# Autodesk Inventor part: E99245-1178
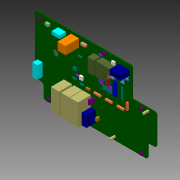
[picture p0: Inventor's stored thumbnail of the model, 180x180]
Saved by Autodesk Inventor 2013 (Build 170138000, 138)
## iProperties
Created: 2004-11
Part Number: E99245-1178
Document SubType Name: Modeling
Designer: Autodesk, Inc.
Manufacturer: Standard
Standards Organization: Custom
Description: CONTROLER CARD, 29 SERIES
Engineer: N. GINEER
Mass: 79.5696 g
Surface Area: 565.686 cm^2
Volume: 79.5696 cm^3
Density: 1 g/cm^3
Material: Allgemein
CAGE: 1LJX3
Dept. ID: Product Design
Description #2: ---
Finish #1: ---
Finish #2: ---
Material ID: ---
Project Number: ---
Author: Autodesk, Inc.
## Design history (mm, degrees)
sketch "Sketch1"
  geometry: L1 (182, 2)-(182, 20); L2 (182, 20)-(185, 23); L3 (185, 23)-(194, 23); L4 (194, 23)-(196, 25); L5 (196, 25)-(196, 70); L6 (196, 70)-(194, 72); L7 (194, 72)-(158.5, 72); L8 (157, 73.5)-(157, 116); L9 (157, 116)-(155, 118); L10 (155, 118)-(2, 118); L11 (2, 118)-(0, 116); L12 (0, 116)-(0, 25); L13 (0, 25)-(2, 23); L14 (2, 23)-(11, 23); L15 (11, 23)-(14, 20); L16 (14, 20)-(14, 2); L17 (14, 2)-(16, 0); L18 (16, 0)-(180, 0); L19 (180, 0)-(182, 2); C1 r 1.753 at (22.987, 3.988); C2 r 1.753 at (172.999, 3.988); C3 r 1.753 at (172.999, 66.98); C4 r 1.753 at (113.005, 113.995); C5 r 1.753 at (8.992, 110.007); C6 r 0.508 at (137.312, 106.68); C7 r 0.508 at (152.248, 106.68); C8 r 0.394 at (103.505, 19.685); C9 r 0.394 at (103.505, 17.145); C10 r 0.508 at (94.615, 25.883); C11 r 0.508 at (94.615, 10.947); C12 r 0.483 at (83.82, 41.275); C13 r 0.483 at (83.82, 12.065); C14 r 0.394 at (95.25, 42.545); C15 r 0.394 at (95.25, 37.465); C16 r 0.483 at (69.85, 41.275); C17 r 0.483 at (69.85, 12.065); C18 r 0.394 at (61.595, 17.145); C19 r 0.394 at (61.595, 12.065); C20 r 0.483 at (53.34, 41.275); C21 r 0.483 at (53.34, 12.065); C22 r 0.635 at (100.33, 109.22); C23 r 0.635 at (100.33, 78.74); C24 r 0.635 at (106.045, 100.965); C25 r 0.635 at (136.525, 100.965); C26 r 0.635 at (113.665, 109.855); C27 r 0.635 at (113.665, 79.375); C28 r 0.432 at (62.23, 107.315); C29 r 0.432 at (67.31, 107.315); C30 r 0.356 at (120.65, 107.95); C31 r 0.356 at (120.65, 97.79); C32 r 0.533 at (73.66, 110.49); C33 r 0.533 at (87.63, 110.49); C34 r 0.508 at (16.51, 109.855); C35 r 0.508 at (27.94, 109.855); C36 r 0.711 at (55.245, 109.855); C37 r 0.711 at (50.165, 109.855); C38 r 0.711 at (37.465, 109.855); C39 r 0.711 at (32.385, 109.855); C40 r 0.432 at (127, 81.28); C41 r 0.432 at (127, 78.74); C42 r 0.432 at (127, 76.2); C43 r 0.432 at (127, 73.66); C44 r 0.432 at (127, 71.12); C45 r 0.432 at (127, 68.58); C46 r 0.432 at (127, 66.04); C47 r 0.432 at (134.62, 66.04); C48 r 0.432 at (134.62, 68.58); C49 r 0.432 at (134.62, 71.12); C50 r 0.432 at (134.62, 73.66); C51 r 0.432 at (134.62, 76.2); C52 r 0.432 at (134.62, 78.74); C53 r 0.432 at (134.62, 81.28); C54 r 0.432 at (115.57, 81.915); C55 r 0.432 at (115.57, 79.375); C56 r 0.432 at (115.57, 76.835); C57 r 0.432 at (115.57, 74.295); C58 r 0.432 at (123.19, 74.295); C59 r 0.432 at (123.19, 76.835); C60 r 0.432 at (123.19, 79.375); C61 r 0.432 at (123.19, 81.915); C62 r 0.47 at (129.413, 5.715); C63 r 0.47 at (183.515, 68.58); C64 r 0.47 at (126.365, 92.71); A1 r 1.5 centre (158.5, 73.5) between (157, 73.5) and (158.5, 72)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
  constraints: 148 centre point, 38 end point, 2 point on circle
extrude "example2.max_Outline" join sketch "Sketch1" distance "d0" = 1.5748; taper "d1" = 0 deg
sketch "3.5MTH, 0_1"
  geometry: L1 (21.082, 2.083)-(21.082, 5.893); L2 (21.082, 5.893)-(24.892, 5.893); L3 (24.892, 5.893)-(24.892, 2.083); L4 (24.892, 2.083)-(21.082, 2.083)
  constraints: 8 end point
extrude "11_2" join sketch "3.5MTH, 0_1" distance "d58" = 2.54; taper "d59" = 0 deg
sketch "3.5MTH, 0_3"
  geometry: L1 (171.094, 2.083)-(171.094, 5.893); L2 (171.094, 5.893)-(174.904, 5.893); L3 (174.904, 5.893)-(174.904, 2.083); L4 (174.904, 2.083)-(171.094, 2.083)
  constraints: 8 end point
extrude "21_4" join sketch "3.5MTH, 0_3" distance "d60" = 2.54; taper "d61" = 0 deg
sketch "3.5MTH, 0_5"
  geometry: L1 (171.094, 65.075)-(171.094, 68.885); L2 (171.094, 68.885)-(174.904, 68.885); L3 (174.904, 68.885)-(174.904, 65.075); L4 (174.904, 65.075)-(171.094, 65.075)
  constraints: 8 end point
extrude "31_6" join sketch "3.5MTH, 0_5" distance "d62" = 2.54; taper "d63" = 0 deg
sketch "3.5MTH, 0_7"
  geometry: L1 (111.1, 112.09)-(111.1, 115.9); L2 (111.1, 115.9)-(114.91, 115.9); L3 (114.91, 115.9)-(114.91, 112.09); L4 (114.91, 112.09)-(111.1, 112.09)
  constraints: 8 end point
extrude "41_8" join sketch "3.5MTH, 0_7" distance "d64" = 2.54; taper "d65" = 0 deg
sketch "3.5MTH, 0_9"
  geometry: L1 (7.087, 108.102)-(7.087, 111.912); L2 (7.087, 111.912)-(10.897, 111.912); L3 (10.897, 111.912)-(10.897, 108.102); L4 (10.897, 108.102)-(7.087, 108.102)
  constraints: 8 end point
extrude "51_10" join sketch "3.5MTH, 0_9" distance "d66" = 2.54; taper "d67" = 0 deg
sketch "RAD_.725X.300_LS.588_.040, 470NF_11"
  geometry: L1 (153.67, 110.49)-(135.89, 110.49); L2 (135.89, 110.49)-(135.89, 102.87); L3 (135.89, 102.87)-(153.67, 102.87); L4 (153.67, 102.87)-(153.67, 110.49)
  constraints: 8 end point
extrude "C1_12" join sketch "RAD_.725X.300_LS.588_.040, 470NF_11" distance "d68" = 15.24; taper "d69" = 0 deg
sketch "SM_C_1206, 10NF_13"
  geometry: L1 (117.602, 62.865)-(119.888, 62.865); L2 (119.888, 62.865)-(119.888, 68.453); L3 (119.888, 68.453)-(117.602, 68.453); L4 (117.602, 68.453)-(117.602, 62.865)
  constraints: 8 end point
extrude "C2_14" join sketch "SM_C_1206, 10NF_13" distance "d70" = 1.27; taper "d71" = 0 deg
sketch "SM_C_1206, 10NF_15"
  geometry: L1 (105.918, 75.565)-(103.632, 75.565); L2 (103.632, 75.565)-(103.632, 69.977); L3 (103.632, 69.977)-(105.918, 69.977); L4 (105.918, 69.977)-(105.918, 75.565)
  constraints: 8 end point
extrude "C3_16" join sketch "SM_C_1206, 10NF_15" distance "d72" = 1.27; taper "d73" = 0 deg
sketch "SM_C_1206, 10NF_17"
  geometry: L1 (112.268, 68.58)-(109.982, 68.58); L2 (109.982, 68.58)-(109.982, 62.992); L3 (109.982, 62.992)-(112.268, 62.992); L4 (112.268, 62.992)-(112.268, 68.58)
  constraints: 8 end point
extrude "C4_18" join sketch "SM_C_1206, 10NF_17" distance "d74" = 1.27; taper "d75" = 0 deg
sketch "SM_C_1206, 10NF_19"
  geometry: L1 (115.062, 62.865)-(117.348, 62.865); L2 (117.348, 62.865)-(117.348, 68.453); L3 (117.348, 68.453)-(115.062, 68.453); L4 (115.062, 68.453)-(115.062, 62.865)
  constraints: 8 end point
extrude "C5_20" join sketch "SM_C_1206, 10NF_19" distance "d76" = 1.27; taper "d77" = 0 deg
sketch "SM_C_1206, 10NF_21"
  geometry: L1 (62.23, 70.993)-(62.23, 68.707); L2 (62.23, 68.707)-(67.818, 68.707); L3 (67.818, 68.707)-(67.818, 70.993); L4 (67.818, 70.993)-(62.23, 70.993)
  constraints: 8 end point
extrude "C6_22" join sketch "SM_C_1206, 10NF_21" distance "d78" = 1.27; taper "d79" = 0 deg
sketch "SM_C_1206, 10NF_23"
  geometry: L1 (62.23, 68.453)-(62.23, 66.167); L2 (62.23, 66.167)-(67.818, 66.167); L3 (67.818, 66.167)-(67.818, 68.453); L4 (67.818, 68.453)-(62.23, 68.453)
  constraints: 8 end point
extrude "C7_24" join sketch "SM_C_1206, 10NF_23" distance "d80" = 1.27; taper "d81" = 0 deg
sketch "SM_C_1206, 10NF_25"
  geometry: L1 (73.66, 53.213)-(73.66, 50.927); L2 (73.66, 50.927)-(79.248, 50.927); L3 (79.248, 50.927)-(79.248, 53.213); L4 (79.248, 53.213)-(73.66, 53.213)
  constraints: 8 end point
extrude "C8_26" join sketch "SM_C_1206, 10NF_25" distance "d82" = 1.27; taper "d83" = 0 deg
sketch "SM_C_1206, 10NF_27"
  geometry: L1 (136.017, 95.885)-(138.303, 95.885); L2 (138.303, 95.885)-(138.303, 101.473); L3 (138.303, 101.473)-(136.017, 101.473); L4 (136.017, 101.473)-(136.017, 95.885)
  constraints: 8 end point
extrude "C9_28" join sketch "SM_C_1206, 10NF_27" distance "d84" = 1.27; taper "d85" = 0 deg
sketch "RAD_.150X.100_LS.100_.031, 1NF_29"
  geometry: L1 (102.133, 20.726)-(102.133, 16.104); L2 (102.133, 16.104)-(104.877, 16.104); L3 (104.877, 16.104)-(104.877, 20.726); L4 (104.877, 20.726)-(102.133, 20.726)
  constraints: 8 end point
extrude "C10_30" join sketch "RAD_.150X.100_LS.100_.031, 1NF_29" distance "d86" = 5.08; taper "d87" = 0 deg
sketch "RAD_.725X.300_LS.588_.040, 470NF_31"
  geometry: L1 (98.425, 9.525)-(98.425, 27.305); L2 (98.425, 27.305)-(90.805, 27.305); L3 (90.805, 27.305)-(90.805, 9.525); L4 (90.805, 9.525)-(98.425, 9.525)
  constraints: 8 end point
extrude "C11_32" join sketch "RAD_.725X.300_LS.588_.040, 470NF_31" distance "d88" = 15.24; taper "d89" = 0 deg
sketch "RAD_1.200X.250_LS1.100_.040, 2.2UF_33"
  geometry: L1 (77.216, 44.069)-(90.424, 44.069); L2 (90.424, 44.069)-(90.424, 9.271); L3 (90.424, 9.271)-(77.216, 9.271); L4 (77.216, 9.271)-(77.216, 44.069)
  constraints: 8 end point
extrude "C12_34" join sketch "RAD_1.200X.250_LS1.100_.040, 2.2UF_33" distance "d90" = 20.828; taper "d91" = 0 deg
sketch "RAD_.300X.100_LS.200_.031, 100PF_35"
  geometry: L1 (93.98, 36.195)-(93.98, 43.815); L2 (93.98, 43.815)-(96.52, 43.815); L3 (96.52, 43.815)-(96.52, 36.195); L4 (96.52, 36.195)-(93.98, 36.195)
  constraints: 8 end point
extrude "C13_36" join sketch "RAD_.300X.100_LS.200_.031, 100PF_35" distance "d92" = 8.255; taper "d93" = 0 deg
sketch "RAD_1.200X.250_LS1.100_.040, 2.2UF_37"
  geometry: L1 (63.246, 44.069)-(76.454, 44.069); L2 (76.454, 44.069)-(76.454, 9.271); L3 (76.454, 9.271)-(63.246, 9.271); L4 (63.246, 9.271)-(63.246, 44.069)
  constraints: 8 end point
extrude "C14_38" join sketch "RAD_1.200X.250_LS1.100_.040, 2.2UF_37" distance "d94" = 20.828; taper "d95" = 0 deg
sketch "RAD_.300X.100_LS.200_.031, 100PF_39"
  geometry: L1 (60.325, 10.795)-(60.325, 18.415); L2 (60.325, 18.415)-(62.865, 18.415); L3 (62.865, 18.415)-(62.865, 10.795); L4 (62.865, 10.795)-(60.325, 10.795)
  constraints: 8 end point
extrude "C15_40" join sketch "RAD_.300X.100_LS.200_.031, 100PF_39" distance "d96" = 8.255; taper "d97" = 0 deg
sketch "RAD_1.200X.250_LS1.100_.040, 2.2UF_41"
  geometry: L1 (46.736, 44.069)-(59.944, 44.069); L2 (59.944, 44.069)-(59.944, 9.271); L3 (59.944, 9.271)-(46.736, 9.271); L4 (46.736, 9.271)-(46.736, 44.069)
  constraints: 8 end point
extrude "C16_42" join sketch "RAD_1.200X.250_LS1.100_.040, 2.2UF_41" distance "d98" = 20.828; taper "d99" = 0 deg
sketch "SM_C_1206, 10NF_43"
  geometry: L1 (120.142, 62.865)-(122.428, 62.865); L2 (122.428, 62.865)-(122.428, 68.453); L3 (122.428, 68.453)-(120.142, 68.453); L4 (120.142, 68.453)-(120.142, 62.865)
  constraints: 8 end point
extrude "C17_44" join sketch "SM_C_1206, 10NF_43" distance "d100" = 1.27; taper "d101" = 0 deg
sketch "SM_C_1206, 10NF_45"
  geometry: L1 (111.252, 75.565)-(113.538, 75.565); L2 (113.538, 75.565)-(113.538, 81.153); L3 (113.538, 81.153)-(111.252, 81.153); L4 (111.252, 81.153)-(111.252, 75.565)
  constraints: 8 end point
extrude "C18_46" join sketch "SM_C_1206, 10NF_45" distance "d102" = 1.27; taper "d103" = 0 deg
sketch "SM_C_1206, 10NF_47"
  geometry: L1 (114.808, 68.58)-(112.522, 68.58); L2 (112.522, 68.58)-(112.522, 62.992); L3 (112.522, 62.992)-(114.808, 62.992); L4 (114.808, 62.992)-(114.808, 68.58)
  constraints: 8 end point
extrude "C19_48" join sketch "SM_C_1206, 10NF_47" distance "d104" = 1.27; taper "d105" = 0 deg
sketch "SM_C_1206, 10NF_49"
  geometry: L1 (142.748, 80.645)-(140.462, 80.645); L2 (140.462, 80.645)-(140.462, 75.057); L3 (140.462, 75.057)-(142.748, 75.057); L4 (142.748, 75.057)-(142.748, 80.645)
  constraints: 8 end point
extrude "C20_50" join sketch "SM_C_1206, 10NF_49" distance "d106" = 1.27; taper "d107" = 0 deg
sketch "SM_C_1206, 10NF_51"
  geometry: L1 (67.31, 53.467)-(67.31, 55.753); L2 (67.31, 55.753)-(61.722, 55.753); L3 (61.722, 55.753)-(61.722, 53.467); L4 (61.722, 53.467)-(67.31, 53.467)
  constraints: 8 end point
extrude "C21_52" join sketch "SM_C_1206, 10NF_51" distance "d108" = 1.27; taper "d109" = 0 deg
sketch "SM_C_1206, 10NF_53"
  geometry: L1 (142.748, 74.93)-(140.462, 74.93); L2 (140.462, 74.93)-(140.462, 69.342); L3 (140.462, 69.342)-(142.748, 69.342); L4 (142.748, 69.342)-(142.748, 74.93)
  constraints: 8 end point
extrude "C22_54" join sketch "SM_C_1206, 10NF_53" distance "d110" = 1.27; taper "d111" = 0 deg
sketch "SM_C_1206, 10NF_55"
  geometry: L1 (142.748, 69.215)-(140.462, 69.215); L2 (140.462, 69.215)-(140.462, 63.627); L3 (140.462, 63.627)-(142.748, 63.627); L4 (142.748, 63.627)-(142.748, 69.215)
  constraints: 8 end point
extrude "C23_56" join sketch "SM_C_1206, 10NF_55" distance "d112" = 1.27; taper "d113" = 0 deg
sketch "SM_C_1206, 10NF_57"
  geometry: L1 (122.682, 62.865)-(124.968, 62.865); L2 (124.968, 62.865)-(124.968, 68.453); L3 (124.968, 68.453)-(122.682, 68.453); L4 (122.682, 68.453)-(122.682, 62.865)
  constraints: 8 end point
extrude "C24_58" join sketch "SM_C_1206, 10NF_57" distance "d114" = 1.27; taper "d115" = 0 deg
sketch "SM_C_1206, 10NF_59"
  geometry: L1 (99.06, 83.312)-(99.06, 85.598); L2 (99.06, 85.598)-(93.472, 85.598); L3 (93.472, 85.598)-(93.472, 83.312); L4 (93.472, 83.312)-(99.06, 83.312)
  constraints: 8 end point
extrude "C25_60" join sketch "SM_C_1206, 10NF_59" distance "d116" = 1.27; taper "d117" = 0 deg
sketch "SM_C_1206, 10NF_61"
  geometry: L1 (76.479, 88.57)-(76.479, 90.856); L2 (76.479, 90.856)-(70.891, 90.856); L3 (70.891, 90.856)-(70.891, 88.57); L4 (70.891, 88.57)-(76.479, 88.57)
  constraints: 8 end point
extrude "C26_62" join sketch "SM_C_1206, 10NF_61" distance "d118" = 1.27; taper "d119" = 0 deg
sketch "AX_1.200X.400_.050, 10UF_63"
  geometry: L1 (95.25, 82.867)-(95.25, 105.092); L2 (95.25, 105.092)-(105.41, 105.093); L3 (105.41, 105.093)-(105.41, 82.868); L4 (105.41, 82.868)-(95.25, 82.867)
  constraints: 8 end point
extrude "C27_64" join sketch "AX_1.200X.400_.050, 10UF_63" distance "d120" = 10.16; taper "d121" = 0 deg
sketch "AX_1.200X.400_.050, 10UF_65"
  geometry: L1 (132.398, 95.885)-(110.173, 95.885); L2 (110.173, 95.885)-(110.173, 106.045); L3 (110.173, 106.045)-(132.398, 106.045); L4 (132.398, 106.045)-(132.398, 95.885)
  constraints: 8 end point
extrude "C28_66" join sketch "AX_1.200X.400_.050, 10UF_65" distance "d122" = 10.16; taper "d123" = 0 deg
sketch "AX_1.200X.400_.050, 10UF_67"
  geometry: L1 (108.585, 83.502)-(108.585, 105.727); L2 (108.585, 105.727)-(118.745, 105.728); L3 (118.745, 105.728)-(118.745, 83.503); L4 (118.745, 83.503)-(108.585, 83.502)
  constraints: 8 end point
extrude "C30_68" join sketch "AX_1.200X.400_.050, 10UF_67" distance "d124" = 10.16; taper "d125" = 0 deg
sketch "CAPTEST, 1MF_69"
  geometry: L1 (58.318, 100.863)-(58.318, 113.767); L2 (58.318, 113.767)-(71.222, 113.767); L3 (71.222, 113.767)-(71.222, 100.863); L4 (71.222, 100.863)-(58.318, 100.863)
  constraints: 8 end point
extrude "C31_70" join sketch "CAPTEST, 1MF_69" distance "d126" = 21.59; taper "d127" = 0 deg
sketch "SM_D_MLL41_12, LL4148_71"
  geometry: L1 (106.68, 83.337)-(106.68, 76.378); L2 (106.68, 76.378)-(108.382, 76.378); L3 (108.382, 76.378)-(108.585, 76.175); L4 (108.585, 76.175)-(108.788, 76.378); L5 (108.788, 76.378)-(110.465, 76.378); L6 (110.465, 76.378)-(110.465, 83.337); L7 (110.465, 83.337)-(106.68, 83.337)
  constraints: 14 end point
extrude "D1_72" join sketch "SM_D_MLL41_12, LL4148_71" distance "d128" = 1.651; taper "d129" = 0 deg
sketch "SM_D_MLL41_12, LL4148_75"
  geometry: L1 (135.255, 97.003)-(135.255, 103.962); L2 (135.255, 103.962)-(133.553, 103.962); L3 (133.553, 103.962)-(133.35, 104.165); L4 (133.35, 104.165)-(133.147, 103.962); L5 (133.147, 103.962)-(131.47, 103.962); L6 (131.47, 103.962)-(131.47, 97.003); L7 (131.47, 97.003)-(135.255, 97.003)
  constraints: 14 end point
extrude "D3_76" join sketch "SM_D_MLL41_12, LL4148_75" distance "d132" = 1.651; taper "d133" = 0 deg
sketch "SM_D_MLL41_12, LL4148_77"
  geometry: L1 (139.065, 101.752)-(139.065, 94.793); L2 (139.065, 94.793)-(140.767, 94.793); L3 (140.767, 94.793)-(140.97, 94.59); L4 (140.97, 94.59)-(141.173, 94.793); L5 (141.173, 94.793)-(142.85, 94.793); L6 (142.85, 94.793)-(142.85, 101.752); L7 (142.85, 101.752)-(139.065, 101.752)
  constraints: 14 end point
extrude "D4_78" join sketch "SM_D_MLL41_12, LL4148_77" distance "d134" = 1.651; taper "d135" = 0 deg
sketch "SM_D_MLL41_12, LL4148_79"
  geometry: L1 (119.863, 86.995)-(126.822, 86.995); L2 (126.822, 86.995)-(126.822, 88.697); L3 (126.822, 88.697)-(127.025, 88.9); L4 (127.025, 88.9)-(126.822, 89.103); L5 (126.822, 89.103)-(126.822, 90.78); L6 (126.822, 90.78)-(119.863, 90.78); L7 (119.863, 90.78)-(119.863, 86.995)
  constraints: 14 end point
extrude "D5_80" join sketch "SM_D_MLL41_12, LL4148_79" distance "d136" = 1.651; taper "d137" = 0 deg
sketch "SM_D_MLL41_12, LL4148_81"
  geometry: L1 (94.463, 90.17)-(101.422, 90.17); L2 (101.422, 90.17)-(101.422, 91.872); L3 (101.422, 91.872)-(101.625, 92.075); L4 (101.625, 92.075)-(101.422, 92.278); L5 (101.422, 92.278)-(101.422, 93.955); L6 (101.422, 93.955)-(94.463, 93.955); L7 (94.463, 93.955)-(94.463, 90.17)
  constraints: 14 end point
extrude "D8_82" join sketch "SM_D_MLL41_12, LL4148_81" distance "d138" = 1.651; taper "d139" = 0 deg
sketch "DAX1_1N_4001-4007, 1N4002_83"
  geometry: L1 (84.455, 108.903)-(84.455, 112.078); L2 (84.455, 112.078)-(76.835, 112.078); L3 (76.835, 112.078)-(76.835, 108.903); L4 (76.835, 108.903)-(84.455, 108.903)
  constraints: 8 end point
extrude "D9_84" join sketch "DAX1_1N_4001-4007, 1N4002_83" distance "d140" = 3.556; taper "d141" = 0 deg
sketch "DAX1_.450X.150_.040, SB130_85"
  geometry: L1 (25.083, 107.95)-(25.083, 111.76); L2 (25.083, 111.76)-(19.367, 111.76); L3 (19.367, 111.76)-(19.367, 107.95); L4 (19.367, 107.95)-(25.083, 107.95)
  constraints: 8 end point
extrude "D10_86" join sketch "DAX1_.450X.150_.040, SB130_85" distance "d142" = 3.81; taper "d143" = 0 deg
sketch "SM_D_MLL41_12, LL4148_87"
  geometry: L1 (117.323, 68.58)-(124.282, 68.58); L2 (124.282, 68.58)-(124.282, 70.282); L3 (124.282, 70.282)-(124.485, 70.485); L4 (124.485, 70.485)-(124.282, 70.688); L5 (124.282, 70.688)-(124.282, 72.365); L6 (124.282, 72.365)-(117.323, 72.365); L7 (117.323, 72.365)-(117.323, 68.58)
  constraints: 14 end point
extrude "D11_88" join sketch "SM_D_MLL41_12, LL4148_87" distance "d144" = 1.651; taper "d145" = 0 deg
sketch "SM_D_MLL41_12, LL4148_89"
  geometry: L1 (106.68, 75.717)-(106.68, 68.758); L2 (106.68, 68.758)-(108.382, 68.758); L3 (108.382, 68.758)-(108.585, 68.555); L4 (108.585, 68.555)-(108.788, 68.758); L5 (108.788, 68.758)-(110.465, 68.758); L6 (110.465, 68.758)-(110.465, 75.717); L7 (110.465, 75.717)-(106.68, 75.717)
  constraints: 14 end point
extrude "D12_90" join sketch "SM_D_MLL41_12, LL4148_89" distance "d146" = 1.651; taper "d147" = 0 deg
sketch "FUSE_20X5, 1A_91"
  geometry: L1 (50.165, 112.395)-(37.465, 112.395); L2 (37.465, 112.395)-(37.465, 107.315); L3 (37.465, 107.315)-(50.165, 107.315); L4 (50.165, 107.315)-(50.165, 112.395)
  constraints: 8 end point
extrude "F1_92" join sketch "FUSE_20X5, 1A_91" distance "d148" = 10.16; taper "d149" = 0 deg
sketch "DIP.100_14_W.300_L.800, CA3046_93"
  geometry: L1 (133.35, 83.82)-(133.35, 63.5); L2 (133.35, 63.5)-(128.27, 63.5); L3 (128.27, 63.5)-(128.27, 83.82); L4 (128.27, 83.82)-(129.54, 83.82); L5 (129.54, 83.82)-(132.08, 83.82); L6 (132.08, 83.82)-(133.35, 83.82)
  constraints: 12 end point
extrude "IC1_94" join sketch "DIP.100_14_W.300_L.800, CA3046_93" distance "d150" = 2.54; taper "d151" = 0 deg
sketch "SOG.050_8_WG.244_L.200, CA3140_95"
  geometry: L1 (67.945, 62.497)-(67.945, 60.592); L2 (67.945, 60.592)-(73.025, 60.592); L3 (73.025, 60.592)-(73.025, 62.497); L4 (73.025, 62.497)-(67.945, 62.497)
  constraints: 8 end point
extrude "IC2_96" join sketch "SOG.050_8_WG.244_L.200, CA3140_95" distance "d152" = 1.651; taper "d153" = 0 deg
sketch "DIP.100_8_W.300_L.400, LF411_97"
  geometry: L1 (121.92, 83.185)-(116.84, 83.185); L2 (116.84, 83.185)-(116.84, 73.025); L3 (116.84, 73.025)-(121.92, 73.025); L4 (121.92, 73.025)-(121.92, 83.185)
  constraints: 8 end point
extrude "IC3_98" join sketch "DIP.100_8_W.300_L.400, LF411_97" distance "d154" = 3.81; taper "d155" = 0 deg
sketch "SOG.050_8_WG.244_L.200, CA3140_99"
  geometry: L1 (104.14, 109.487)-(104.14, 107.582); L2 (104.14, 107.582)-(109.22, 107.582); L3 (109.22, 107.582)-(109.22, 109.487); L4 (109.22, 109.487)-(104.14, 109.487)
  constraints: 8 end point
extrude "IC4_100" join sketch "SOG.050_8_WG.244_L.200, CA3140_99" distance "d156" = 1.651; taper "d157" = 0 deg
sketch "BLKCON.100_VH_TM1SQ_W.100_1, PL,1WAY,110,V_101"
  geometry: L1 (130.683, 6.985)-(128.143, 6.985); L2 (128.143, 6.985)-(128.143, 4.445); L3 (128.143, 4.445)-(130.683, 4.445); L4 (130.683, 4.445)-(130.683, 6.985)
  constraints: 8 end point
extrude "PL1_102" join sketch "BLKCON.100_VH_TM1SQ_W.100_1, PL,1WAY,110,V_101" distance "d158" = 8.89; taper "d159" = 0 deg
sketch "BLKCON.100_VH_TM1SQ_W.100_1, PL,1WAY,110,V_103"
  geometry: L1 (184.785, 69.85)-(182.245, 69.85); L2 (182.245, 69.85)-(182.245, 67.31); L3 (182.245, 67.31)-(184.785, 67.31); L4 (184.785, 67.31)-(184.785, 69.85)
  constraints: 8 end point
extrude "PL2_104" join sketch "BLKCON.100_VH_TM1SQ_W.100_1, PL,1WAY,110,V_103" distance "d160" = 8.89; taper "d161" = 0 deg
sketch "BLKCON.100_VH_TM1SQ_W.100_4.3, HEADER 4_3_105"
  geometry: L1 (135.255, 93.98)-(125.095, 93.98); L2 (125.095, 93.98)-(125.095, 91.44); L3 (125.095, 91.44)-(135.255, 91.44); L4 (135.255, 91.44)-(135.255, 93.98)
  constraints: 8 end point
extrude "PL3_106" join sketch "BLKCON.100_VH_TM1SQ_W.100_4.3, HEADER 4_3_105" distance "d162" = 8.255; taper "d163" = 0 deg
sketch "BLKCON.100_VH_TM1SQ_W.100_14, HEADER 14_107"
  geometry: L1 (185.42, 28.575)-(185.42, 64.135); L2 (185.42, 64.135)-(187.96, 64.135); L3 (187.96, 64.135)-(187.96, 28.575); L4 (187.96, 28.575)-(185.42, 28.575)
  constraints: 8 end point
extrude "PL4_108" join sketch "BLKCON.100_VH_TM1SQ_W.100_14, HEADER 14_107" distance "d164" = 2.54; taper "d165" = 0 deg
sketch "AX_.400X.100_.031, 330K_109"
  geometry: L1 (83.82, 50.165)-(83.82, 51.435); L2 (83.82, 51.435)-(83.82, 52.705); L3 (83.82, 52.705)-(90.17, 52.705); L4 (90.17, 52.705)-(90.17, 51.435); L5 (90.17, 51.435)-(90.17, 50.165); L6 (90.17, 50.165)-(83.82, 50.165)
  constraints: 12 end point
extrude "R1_110" join sketch "AX_.400X.100_.031, 330K_109" distance "d166" = 2.54; taper "d167" = 0 deg
sketch "AX_.600X.100_.034, 33M_111"
  geometry: L1 (134.302, 52.705)-(134.303, 50.165); L2 (134.303, 50.165)-(145.098, 50.165); L3 (145.098, 50.165)-(145.097, 52.705); L4 (145.097, 52.705)-(134.302, 52.705)
  constraints: 8 end point
extrude "R2_112" join sketch "AX_.600X.100_.034, 33M_111" distance "d168" = 2.54; taper "d169" = 0 deg
sketch "AX_.600X.100_.034, 33M_113"
  geometry: L1 (115.252, 52.705)-(115.253, 50.165); L2 (115.253, 50.165)-(126.048, 50.165); L3 (126.048, 50.165)-(126.047, 52.705); L4 (126.047, 52.705)-(115.252, 52.705)
  constraints: 8 end point
extrude "R3_114" join sketch "AX_.600X.100_.034, 33M_113" distance "d170" = 2.54; taper "d171" = 0 deg
sketch "AX_.600X.100_.034, 33M_115"
  geometry: L1 (96.837, 52.705)-(96.838, 50.165); L2 (96.838, 50.165)-(107.633, 50.165); L3 (107.633, 50.165)-(107.632, 52.705); L4 (107.632, 52.705)-(96.837, 52.705)
  constraints: 8 end point
extrude "R4_116" join sketch "AX_.600X.100_.034, 33M_115" distance "d172" = 2.54; taper "d173" = 0 deg
sketch "SM_R_1206, 30K_119"
  geometry: L1 (144.78, 86.487)-(144.78, 88.773); L2 (144.78, 88.773)-(139.192, 88.773); L3 (139.192, 88.773)-(139.192, 86.487); L4 (139.192, 86.487)-(144.78, 86.487)
  constraints: 8 end point
extrude "R6_120" join sketch "SM_R_1206, 30K_119" distance "d176" = 1.27; taper "d177" = 0 deg
sketch "SM_R_1206, 30K_121"
  geometry: L1 (151.765, 94.742)-(151.765, 97.028); L2 (151.765, 97.028)-(146.177, 97.028); L3 (146.177, 97.028)-(146.177, 94.742); L4 (146.177, 94.742)-(151.765, 94.742)
  constraints: 8 end point
extrude "R7_122" join sketch "SM_R_1206, 30K_121" distance "d178" = 1.27; taper "d179" = 0 deg
sketch "AX_.600X.100_.034, 33M_123"
  geometry: L1 (151.765, 64.453)-(149.225, 64.452); L2 (149.225, 64.452)-(149.225, 53.657); L3 (149.225, 53.657)-(151.765, 53.658); L4 (151.765, 53.658)-(151.765, 64.453)
  constraints: 8 end point
extrude "R8_124" join sketch "AX_.600X.100_.034, 33M_123" distance "d180" = 2.54; taper "d181" = 0 deg
sketch "SM_R_1206, 30K_127"
  geometry: L1 (144.78, 90.297)-(144.78, 92.583); L2 (144.78, 92.583)-(139.192, 92.583); L3 (139.192, 92.583)-(139.192, 90.297); L4 (139.192, 90.297)-(144.78, 90.297)
  constraints: 8 end point
extrude "R10_128" join sketch "SM_R_1206, 30K_127" distance "d184" = 1.27; taper "d185" = 0 deg
sketch "SM_R_1206, 30K_129"
  geometry: L1 (151.765, 98.552)-(151.765, 100.838); L2 (151.765, 100.838)-(146.177, 100.838); L3 (146.177, 100.838)-(146.177, 98.552); L4 (146.177, 98.552)-(151.765, 98.552)
  constraints: 8 end point
extrude "R11_130" join sketch "SM_R_1206, 30K_129" distance "d186" = 1.27; taper "d187" = 0 deg
sketch "VRES36, 500R_135"
  geometry: L1 (78.842, 64.643)-(73.914, 64.643); L2 (73.914, 64.643)-(73.914, 58.814); L3 (73.914, 58.814)-(78.842, 58.814); L4 (78.842, 58.814)-(78.842, 64.643)
  constraints: 8 end point
extrude "R14_136" join sketch "VRES36, 500R_135" distance "d192" = 2.54; taper "d193" = 0 deg
sketch "VRES36, 500R_137"
  geometry: L1 (125.628, 104.902)-(130.556, 104.902); L2 (130.556, 104.902)-(130.556, 110.731); L3 (130.556, 110.731)-(125.628, 110.731); L4 (125.628, 110.731)-(125.628, 104.902)
  constraints: 8 end point
extrude "R15_138" join sketch "VRES36, 500R_137" distance "d194" = 2.54; taper "d195" = 0 deg
sketch "AX_1.000X.325_.037, 30R_205"
  geometry: L1 (12.382, 50.8)-(12.382, 30.48); L2 (12.382, 30.48)-(4.127, 30.48); L3 (4.127, 30.48)-(4.127, 50.8); L4 (4.127, 50.8)-(12.382, 50.8)
  constraints: 8 end point
extrude "R49_206" join sketch "AX_1.000X.325_.037, 30R_205" distance "d262" = 8.255; taper "d263" = 0 deg
body "Solid1"
other parameters: "d2" = 1.5748
